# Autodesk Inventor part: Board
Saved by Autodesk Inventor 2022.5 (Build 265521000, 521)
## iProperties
Created: 2024-07
Part Number: Board
Material: Generic
Document SubType Name: Modeling
Designer: AdminForWorker
Density: 1 g/cm^3
Appearance: Default
Title: Board
Author: AdminForWorker
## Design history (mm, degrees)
feature "Board"
feature "CopperHoles"
body "Solid1"
body "Solid2"
